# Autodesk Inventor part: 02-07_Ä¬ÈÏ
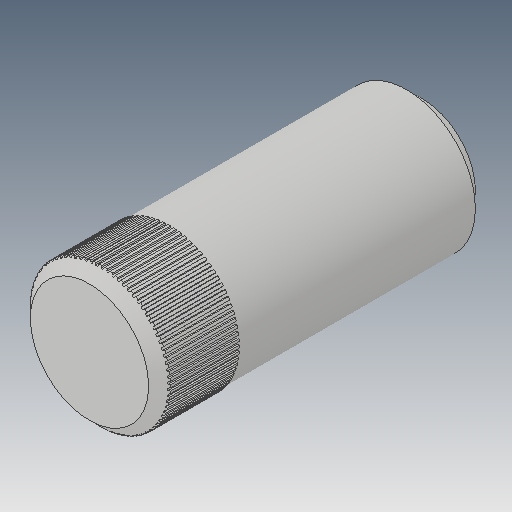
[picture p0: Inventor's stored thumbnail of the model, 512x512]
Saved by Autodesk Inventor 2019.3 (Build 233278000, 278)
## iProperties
Created: 2010-06
Part Number: 02-07_Ä¬ÈÏ
Material: Ogólny
Document SubType Name: Modeling
Designer: CADENGINEERING4
Density: 1 g/cm^3
Appearance: Domyślna
Author: CADENGINEERING4
Revision Number: ÈÎºÎ
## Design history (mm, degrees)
feature "NONE"
node "Bryła1"
